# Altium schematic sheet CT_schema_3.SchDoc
size 296 x 169 mm
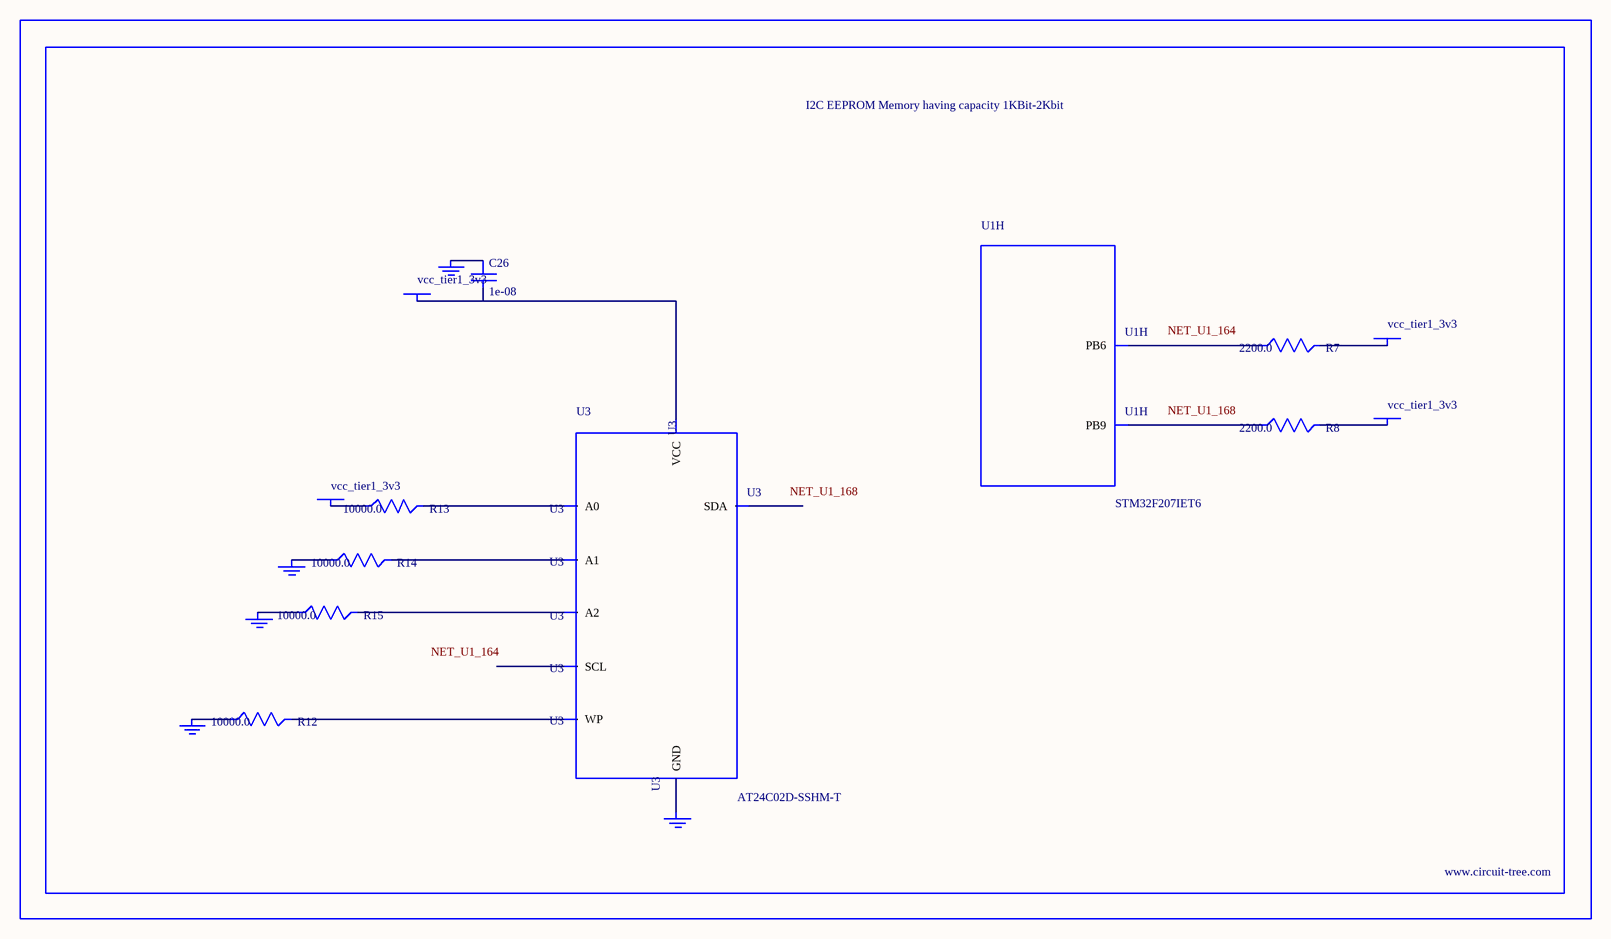
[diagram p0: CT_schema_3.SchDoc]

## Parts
BORDER2  (no value)
C26  1e-08  [C0402]
GND_INSTANCE_2_0  (no value)
GND_INSTANCE_2_1  (no value)
GND_INSTANCE_2_2  (no value)
GND_INSTANCE_2_3  (no value)
GND_INSTANCE_2_4  (no value)
POWER_INSTANCE_2_0  vcc_tier1_3v3
POWER_INSTANCE_2_1  vcc_tier1_3v3
POWER_INSTANCE_2_2  vcc_tier1_3v3
POWER_INSTANCE_2_3  vcc_tier1_3v3
R7  2200.0  [R0603]
R8  2200.0  [R0603]
R12  10000.0  [R0603]
R13  10000.0  [R0603]
R14  10000.0  [R0603]
R15  10000.0  [R0603]
U1  STM32F207IET6  [LQFP176]  (part H of 11)
U3  AT24C02D-SSHM-T  [AT24C02D]

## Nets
NetC26_1: C26.1 GND_INSTANCE_2_3.0(GND)
NetC26_2: C26.2 POWER_INSTANCE_2_1.0(PWR) U3.8(VCC)
NetGND_INSTANCE_2_0_0: GND_INSTANCE_2_0.0(GND) R14.1
NetGND_INSTANCE_2_1_0: GND_INSTANCE_2_1.0(GND) R15.1
NetGND_INSTANCE_2_2_0: GND_INSTANCE_2_2.0(GND) R12.1
NetGND_INSTANCE_2_4_0: GND_INSTANCE_2_4.0(GND) U3.4(GND)
NetPOWER_INSTANCE_2_0_0: POWER_INSTANCE_2_0.0(PWR) R13.1
NetPOWER_INSTANCE_2_2_0: POWER_INSTANCE_2_2.0(PWR) R7.2
NetPOWER_INSTANCE_2_3_0: POWER_INSTANCE_2_3.0(PWR) R8.2
NetR7_1: R7.1 U1.164(PB6)
NetR8_1: R8.1 U1.168(PB9)
NetR12_2: R12.2 U3.7(WP)
NetR13_2: R13.2 U3.1(A0)
NetR14_2: R14.2 U3.2(A1)
NetR15_2: R15.2 U3.3(A2)

Not connected (* = marked no-connect by the designer): U3 5(SDA) 6(SCL)

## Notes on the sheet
- Labels drawn without touching a wire or pin: NET_U1_164, NET_U1_168

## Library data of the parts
BORDER2 = BORDER_PAGE2
C26 = C0402C103K3RAC
GND_INSTANCE_2_0-GND_INSTANCE_2_4 = GND
POWER_INSTANCE_2_0-POWER_INSTANCE_2_3 = PWR
R7 R8 = RC0603JR-072K2L
R12-R15 = RC0603JR-0710KL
